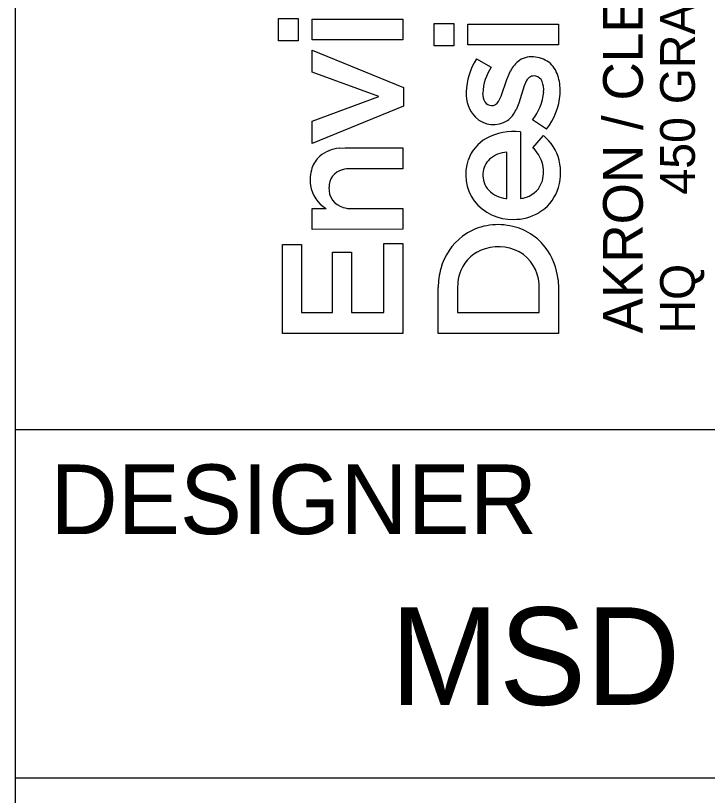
# Model space of a CAD drawing. Extents: x -6.7 to 34, y -3.7 to 22.
# Drawn here: x 32 to 32.993, y 2.475 to 3.594 of the extents above; entities that cross this region are included whole.
import ezdxf

# ---------------------------------------------------------------- set-up
doc = ezdxf.new("R2010")
doc.units = 0
doc.layers.add('SH_Border', color=7, linetype='Continuous')
doc.layers.add('SH_Named_Boundary', color=7, linetype='Continuous')

msp = doc.modelspace()

# ---------------------------------------------------------------- linework, layer by layer
at = {"layer": 'SH_Border'}
for p, q in [((32, 0.5), (32, 21.5)), ((32, 3), (33.5, 3)), ((32, 2.5), (33.5, 2.5))]:
    msp.add_line(p, q, dxfattribs=at)
at = {"layer": 'SH_Named_Boundary'}
for p, q in [((32.3771, 3.5582), (32.3771, 3.5903)), ((32.3771, 3.5903), (32.4054, 3.5903)), ((32.4054, 3.5903), (32.4054, 3.5582)), ((32.4254, 3.5594), (32.4254, 3.5893)), ((32.4254, 3.5893), (32.5557, 3.5893)), ((32.5557, 3.5893), (32.5557, 3.5594)), ((32.6005, 3.5511), (32.6005, 3.5832)), ((32.6005, 3.5832), (32.6289, 3.5832)), ((32.6289, 3.5832), (32.6289, 3.5511)), ((32.6489, 3.5523), (32.6489, 3.5822)), ((32.6489, 3.5822), (32.7792, 3.5822)), ((32.7792, 3.5822), (32.7792, 3.5523)), ((32.4054, 3.5582), (32.3771, 3.5582)), ((32.5557, 3.5594), (32.4254, 3.5594)), ((32.6289, 3.5511), (32.6005, 3.5511)), ((32.7792, 3.5523), (32.6489, 3.5523)), ((32.4254, 3.5133), (32.4254, 3.5446)), ((32.4254, 3.5446), (32.5567, 3.4913)), ((32.6615, 3.5321), (32.6827, 3.5203)), ((32.7048, 3.5026), (32.7104, 3.5153)), ((32.5212, 3.478), (32.4254, 3.5133)), ((32.6967, 3.4787), (32.7048, 3.5026)), ((32.7298, 3.4933), (32.7221, 3.4688)), ((32.7334, 3.501), (32.7298, 3.4933)), ((32.5567, 3.4913), (32.5567, 3.4644)), ((32.4254, 3.4429), (32.5212, 3.478)), ((32.693, 3.4712), (32.6967, 3.4787)), ((32.5567, 3.4644), (32.4254, 3.4109)), ((32.7221, 3.4688), (32.7182, 3.4592)), ((32.4254, 3.4109), (32.4254, 3.4429)), ((32.7621, 3.4314), (32.742, 3.4447)), ((32.7245, 3.4275), (32.7246, 3.3319)), ((32.7423, 3.4046), (32.7577, 3.422)), ((32.4644, 3.404), (32.4729, 3.4044)), ((32.4729, 3.4044), (32.5557, 3.4044)), ((32.5557, 3.4044), (32.5557, 3.3746)), ((32.7049, 3.3318), (32.7049, 3.3983)), ((32.5557, 3.3746), (32.4814, 3.3746)), ((32.7036, 3.3317), (32.7049, 3.3318)), ((32.4254, 3.2875), (32.4254, 3.3173)), ((32.4254, 3.3173), (32.4455, 3.3173)), ((32.4822, 3.3173), (32.5557, 3.3173)), ((32.5557, 3.3173), (32.5557, 3.2876)), ((32.5557, 3.2876), (32.4254, 3.2875)), ((32.383, 3.1379), (32.383, 3.266)), ((32.383, 3.266), (32.4101, 3.266)), ((32.4101, 3.266), (32.4101, 3.1683)), ((32.5286, 3.1683), (32.5286, 3.2672)), ((32.5286, 3.2672), (32.5557, 3.2672)), ((32.5557, 3.2672), (32.5557, 3.1379)), ((32.455, 3.1683), (32.455, 3.2549)), ((32.455, 3.2549), (32.4822, 3.2549)), ((32.4822, 3.2549), (32.4822, 3.1683)), ((32.7785, 3.215), (32.7792, 3.2021)), ((32.6064, 3.138), (32.6064, 3.204)), ((32.6347, 3.2118), (32.6341, 3.2023)), ((32.6341, 3.2023), (32.6341, 3.1684)), ((32.7515, 3.1683), (32.7515, 3.2024)), ((32.7792, 3.2021), (32.7792, 3.138)), ((32.4101, 3.1683), (32.455, 3.1683)), ((32.4822, 3.1683), (32.5286, 3.1683)), ((32.6341, 3.1684), (32.7515, 3.1683)), ((32.5557, 3.1379), (32.383, 3.1379)), ((32.7792, 3.138), (32.6064, 3.138))]:
    msp.add_line(p, q, dxfattribs=at)
for points in [[(32.3771, 3.5582), (32.3771, 3.5903), (32.4054, 3.5903), (32.4054, 3.5582)], [(32.4254, 3.5594), (32.4254, 3.5893), (32.5557, 3.5893), (32.5557, 3.5594)], [(32.6005, 3.5511), (32.6005, 3.5832), (32.6289, 3.5832), (32.6289, 3.5511)], [(32.6489, 3.5523), (32.6489, 3.5822), (32.7792, 3.5822), (32.7792, 3.5523)], [(32.4254, 3.4109), (32.4254, 3.4429), (32.5212, 3.478), (32.4254, 3.5133), (32.4254, 3.5446), (32.5567, 3.4913), (32.5567, 3.4644)], [(32.383, 3.1379), (32.383, 3.266), (32.4101, 3.266), (32.4101, 3.1683), (32.455, 3.1683), (32.455, 3.2549), (32.4822, 3.2549), (32.4822, 3.1683), (32.5286, 3.1683), (32.5286, 3.2672), (32.5557, 3.2672), (32.5557, 3.1379)]]:
    msp.add_lwpolyline(points, close=True, dxfattribs=at)
for points in [[(32.6615, 3.5321), (32.6827, 3.5203)], [(32.693, 3.4712), (32.6967, 3.4787), (32.7048, 3.5026), (32.7104, 3.5153)], [(32.7334, 3.501), (32.7298, 3.4933), (32.7221, 3.4688), (32.7182, 3.4592)], [(32.7621, 3.4314), (32.742, 3.4447)], [(32.7245, 3.4275), (32.7246, 3.3319)], [(32.7423, 3.4046), (32.7577, 3.422)], [(32.4644, 3.404), (32.4729, 3.4044), (32.5557, 3.4044), (32.5557, 3.3746), (32.4814, 3.3746)], [(32.7036, 3.3317), (32.7049, 3.3318), (32.7049, 3.3983)], [(32.4254, 3.2875), (32.4254, 3.3173), (32.4455, 3.3173)], [(32.4822, 3.3173), (32.5557, 3.3173), (32.5557, 3.2876), (32.4254, 3.2875)], [(32.7785, 3.215), (32.7792, 3.2021), (32.7792, 3.138), (32.6064, 3.138)], [(32.6064, 3.138), (32.6064, 3.204)], [(32.6347, 3.2118), (32.6341, 3.2023), (32.6341, 3.1684), (32.7515, 3.1683), (32.7515, 3.2024)]]:
    msp.add_lwpolyline(points, dxfattribs=at)
for centre, radius, start, end in [((32.7364, 3.4826), 0.0897, 146.531, 178.7571), ((32.7364, 3.4826), 0.0897, 146.531, 178.7571), ((32.7466, 3.4971), 0.0405, 125.5118, 153.4159), ((32.7466, 3.4971), 0.0405, 125.5118, 153.4159), ((32.7406, 3.5026), 0.0326, 80.1719, 122.5197), ((32.7406, 3.5026), 0.0326, 80.1719, 122.5197), ((32.7428, 3.4982), 0.0367, 47.7934, 84.6892), ((32.7428, 3.4982), 0.0367, 47.7934, 84.6892), ((32.7452, 3.4789), 0.0749, 146.5112, 176.9101), ((32.7452, 3.4789), 0.0749, 146.5112, 176.9101), ((32.7379, 3.4946), 0.0427, 14.9966, 46.2063), ((32.7379, 3.4946), 0.0427, 14.9966, 46.2063), ((32.7438, 3.4963), 0.0114, 76.6609, 155.7053), ((32.7438, 3.4963), 0.0114, 76.6609, 155.7053), ((32.744, 3.4951), 0.0126, 21.5098, 78.5262), ((32.744, 3.4951), 0.0126, 21.5098, 78.5262), ((32.7104, 3.4867), 0.0712, 355.8306, 15.3914), ((32.7104, 3.4867), 0.0712, 355.8306, 15.3914), ((32.7259, 3.4877), 0.0321, 354.5726, 22.068), ((32.7259, 3.4877), 0.0321, 354.5726, 22.068), ((32.6967, 3.4824), 0.0501, 177.5366, 222.7932), ((32.6967, 3.4824), 0.0501, 177.5366, 222.7932), ((32.6931, 3.4823), 0.0228, 178.4747, 211.0868), ((32.6931, 3.4823), 0.0228, 178.4747, 211.0868), ((32.6825, 3.4915), 0.0757, 321.811, 354.7969), ((32.6825, 3.4915), 0.0757, 321.811, 354.7969), ((32.6895, 3.4882), 0.0922, 321.9777, 355.8738), ((32.6895, 3.4882), 0.0922, 321.9777, 355.8738), ((32.6833, 3.4767), 0.0115, 212.2368, 268.3777), ((32.6833, 3.4767), 0.0115, 212.2368, 268.3777), ((32.6834, 3.4759), 0.0107, 267.716, 333.7337), ((32.6834, 3.4759), 0.0107, 267.716, 333.7337), ((32.681, 3.4758), 0.0408, 308.0877, 335.9874), ((32.681, 3.4758), 0.0408, 308.0877, 335.9874), ((32.686, 3.4753), 0.0375, 225.9854, 302.4797), ((32.686, 3.4753), 0.0375, 225.9854, 302.4797), ((32.7152, 3.3441), 0.0838, 83.615, 118.2876), ((32.7152, 3.3441), 0.0838, 83.615, 118.2876), ((32.7024, 3.3691), 0.0558, 118.8308, 160.6244), ((32.7024, 3.3691), 0.0558, 118.8308, 160.6244), ((32.7174, 3.3717), 0.0644, 13.5336, 51.3615), ((32.7174, 3.3717), 0.0644, 13.5336, 51.3615), ((32.4687, 3.3543), 0.0499, 94.9696, 130.2225), ((32.4687, 3.3543), 0.0499, 94.9696, 130.2225), ((32.7038, 3.3656), 0.0549, 19.0357, 45.4406), ((32.7038, 3.3656), 0.0549, 19.0357, 45.4406), ((32.4635, 3.3626), 0.0402, 132.2219, 161.6818), ((32.4635, 3.3626), 0.0402, 132.2219, 161.6818), ((32.7079, 3.3561), 0.0424, 94.008, 130.8817), ((32.7079, 3.3561), 0.0424, 94.008, 130.8817), ((32.7104, 3.3661), 0.0644, 160.5201, 215.7831), ((32.7104, 3.3661), 0.0644, 160.5201, 215.7831), ((32.7005, 3.3663), 0.0298, 132.9851, 177.179), ((32.7005, 3.3663), 0.0298, 132.9851, 177.179), ((32.7107, 3.3697), 0.047, 344.6059, 17.007), ((32.7107, 3.3697), 0.047, 344.6059, 17.007), ((32.7064, 3.3692), 0.0758, 339.3542, 13.3785), ((32.7064, 3.3692), 0.0758, 339.3542, 13.3785), ((32.4787, 3.3582), 0.056, 162.2736, 187.7919), ((32.4787, 3.3582), 0.056, 162.2736, 187.7919), ((32.4748, 3.3487), 0.025, 103.6865, 182.2187), ((32.4748, 3.3487), 0.025, 103.6865, 182.2187), ((32.4811, 3.3286), 0.046, 89.6049, 105.3284), ((32.4811, 3.3286), 0.046, 89.6049, 105.3284), ((32.7017, 3.365), 0.0311, 175.0013, 223.283), ((32.7017, 3.365), 0.0311, 175.0013, 223.283), ((32.4703, 3.358), 0.0476, 188.962, 238.7037), ((32.4703, 3.358), 0.0476, 188.962, 238.7037), ((32.4773, 3.3456), 0.0276, 175.5854, 255.1439), ((32.4773, 3.3456), 0.0276, 175.5854, 255.1439), ((32.7224, 3.3671), 0.035, 288.0077, 343.5508), ((32.7224, 3.3671), 0.035, 288.0077, 343.5508), ((32.7089, 3.3736), 0.0423, 225.0619, 262.7974), ((32.7089, 3.3736), 0.0423, 225.0619, 262.7974), ((32.7189, 3.3652), 0.0626, 300.9427, 338.7323), ((32.7189, 3.3652), 0.0626, 300.9427, 338.7323), ((32.7125, 3.3705), 0.0687, 217.7452, 271.6543), ((32.7125, 3.3705), 0.0687, 217.7452, 271.6543), ((32.7247, 3.3522), 0.0202, 269.7003, 294.8711), ((32.7247, 3.3522), 0.0202, 269.7003, 294.8711), ((32.4818, 3.3595), 0.0422, 254.0916, 270.5284), ((32.4818, 3.3595), 0.0422, 254.0916, 270.5284), ((32.7155, 3.3724), 0.0706, 269.2048, 300.3341), ((32.7155, 3.3724), 0.0706, 269.2048, 300.3341), ((32.6923, 3.2079), 0.0864, 81.194, 125.9984), ((32.6923, 3.2079), 0.0864, 81.194, 125.9984), ((32.6946, 3.2113), 0.0827, 37.8521, 82.402), ((32.6946, 3.2113), 0.0827, 37.8521, 82.402), ((32.6939, 3.2089), 0.0865, 127.2362, 165.148), ((32.6939, 3.2089), 0.0865, 127.2362, 165.148), ((32.6889, 3.2078), 0.054, 106.1881, 157.3861), ((32.6889, 3.2078), 0.054, 106.1881, 157.3861), ((32.6928, 3.1986), 0.0639, 55.6727, 107.2093), ((32.6928, 3.1986), 0.0639, 55.6727, 107.2093), ((32.6859, 3.2057), 0.0931, 5.7333, 37.304), ((32.6859, 3.2057), 0.0931, 5.7333, 37.304), ((32.6929, 3.205), 0.0587, 357.4662, 52.2665), ((32.6929, 3.205), 0.0587, 357.4662, 52.2665), ((32.7143, 3.2028), 0.1078, 164.7861, 179.3704), ((32.7143, 3.2028), 0.1078, 164.7861, 179.3704), ((32.6983, 3.2039), 0.0641, 157.3571, 172.9275), ((32.6983, 3.2039), 0.0641, 157.3571, 172.9275)]:
    msp.add_arc(centre, radius, start, end, dxfattribs=at)

# ---------------------------------------------------------------- texts
for s, height, p in [('450 GRANT ST., AKRON, OH  44311', 0.049846, (32.9749, 3.3374)), ('AKRON / CLEVELAND / COLUMBUS', 0.056969, (32.9001, 3.138)), ('HQ ', 0.04985, (32.9749, 3.138))]:
    msp.add_text(s, height=height, rotation=90, dxfattribs=at).set_placement(p)
for s, height, p in [('DESIGNER', 0.1, (32.05, 2.85)), ('MSD', 0.14, (32.5379, 2.605))]:
    msp.add_text(s, height=height, dxfattribs=at).set_placement(p)

doc.saveas('drawing.dxf')
